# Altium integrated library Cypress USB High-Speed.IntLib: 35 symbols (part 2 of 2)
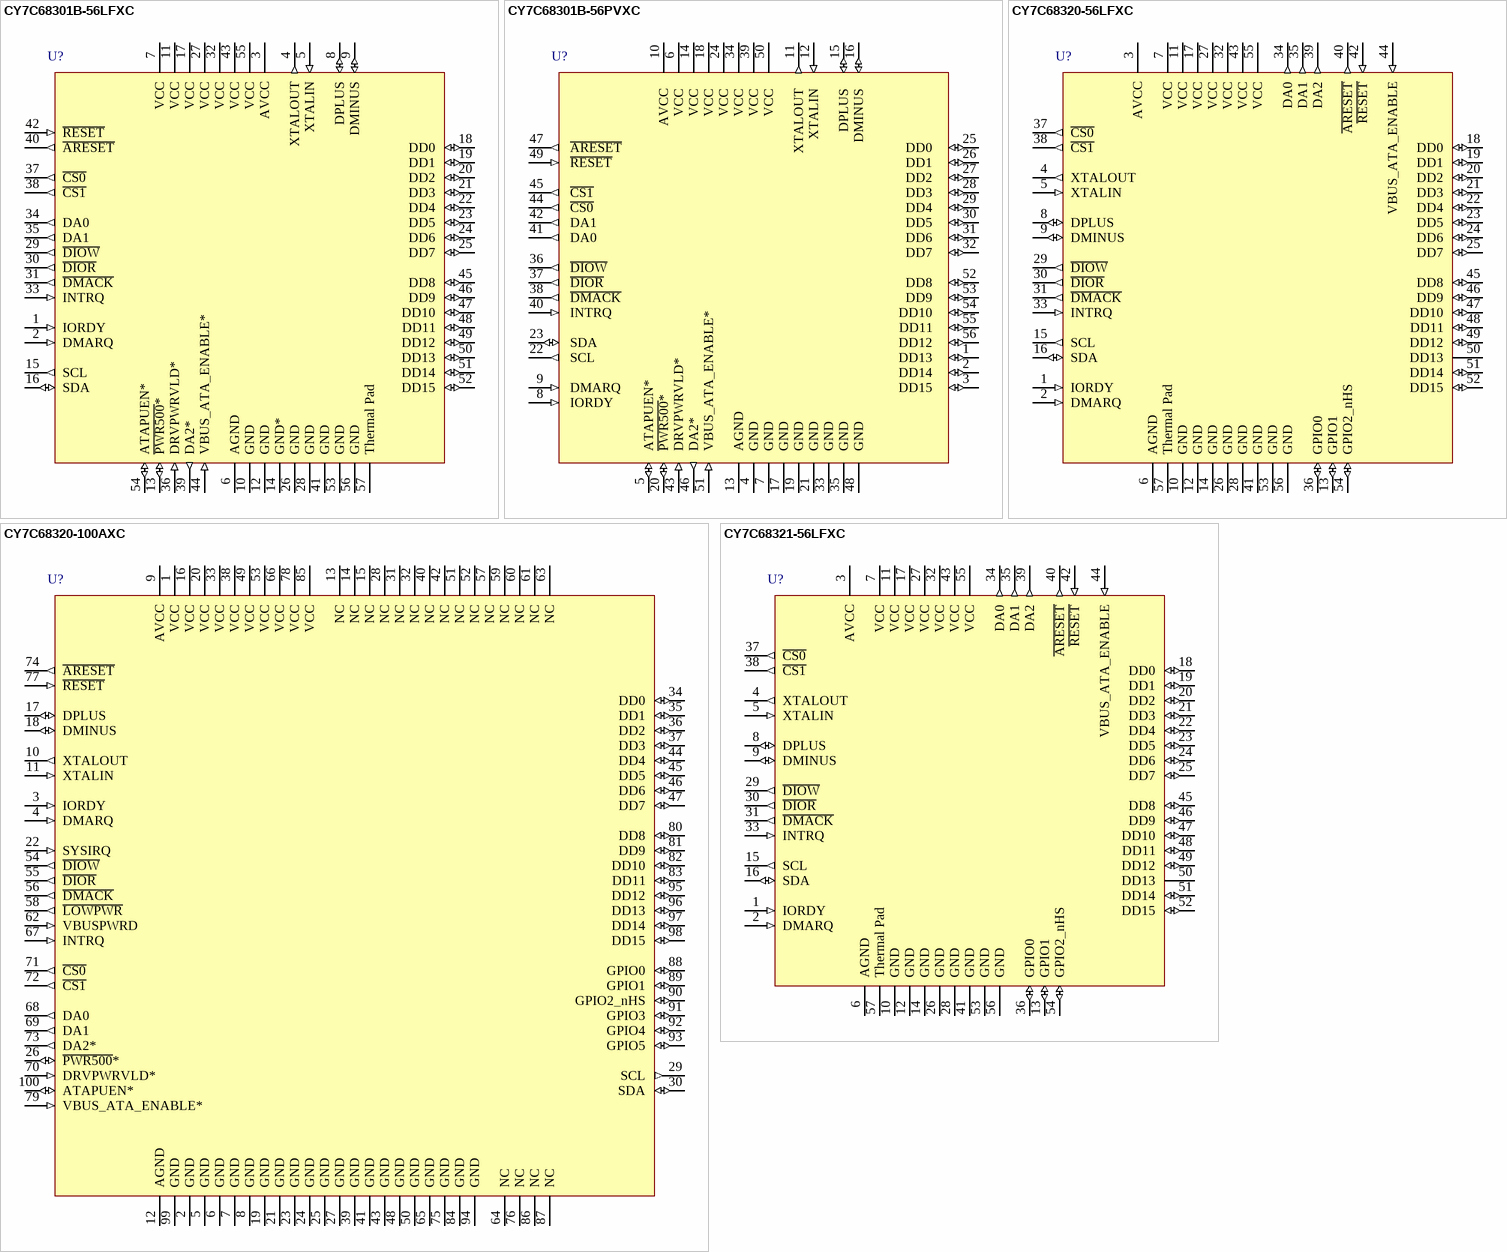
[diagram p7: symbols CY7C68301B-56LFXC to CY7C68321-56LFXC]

## CY7C68301B-56LFXC
designator U?
EZ-USB AT2LP USB2.0 to ATA/ATAPI Bridge for Battery Powered Designs, 56-Pin QFN, Pb-Free; Note: Pin names with Asterisk denote Pin Functionality during CY7C68300A Compatibility mode
footprint LF56A_N (QFN, 56-Leads, Body 8x8mm, Pitch 0.5mm, IPC Medium Density)
footprint LF56A_L (QFN, 56-Leads, Body 8x8mm, Pitch 0.5mm, IPC High Density)
footprint LF56A_M (QFN, 56-Leads, Body 8x8mm, Pitch 0.5mm, IPC Low Density)
pins: 1 IORDY (in), 2 DMARQ (in), 3 AVCC (power), 4 XTALOUT (out), 5 XTALIN (in), 6 AGND (power), 7 VCC (power), 8 DPLUS (io), 9 DMINUS (io), 10 GND (power), 11 VCC (power), 12 GND (power), 13 ~{PWR500}* (io) "(PU 10K)", 14 GND* (power) "(RESERVED)", 15 SCL (out), 16 SDA (io), 17 VCC (power), 18 DD0 (io), 19 DD1 (io), 20 DD2 (io), 21 DD3 (io), 22 DD4 (io), 23 DD5 (io), 24 DD6 (io), 25 DD7 (io), 26 GND (power), 27 VCC (power), 28 GND (power), 29 ~{DIOW} (out), 30 ~{DIOR} (out), 31 ~{DMACK} (out), 32 VCC (power), 33 INTRQ (in), 34 DA0 (out), 35 DA1 (out), 36 DRVPWRVLD* (in) "(DA2)", 37 ~{CS0} (out), 38 ~{CS1} (out), 39 DA2* (out) "(VBUS_PWR_VALID)", 40 ~{ARESET} (out), 41 GND (power), 42 ~{RESET} (in), 43 VCC (power), 44 VBUS_ATA_ENABLE* (in) "(ATA_EN)", 45 DD8 (io), 46 DD9 (io), 47 DD10 (io), 48 DD11 (io), 49 DD12 (io), 50 DD13 (io), 51 DD14 (io), 52 DD15 (io), 53 GND (power), 54 ATAPUEN* (io) "(NC)", 55 VCC (power), 56 GND (power), 57 Thermal Pad (power)

## CY7C68301B-56PVXC
designator U?
EZ-USB AT2LP USB2.0 to ATA/ATAPI Bridge for Battery Powered Designs, 56-Pin SSOP, Pb-Free; Note: Pin names with Asterisk denote Pin Functionality during CY7C68300A Compatibility mode
footprint O56 (SSOP; 56 Leads; Body Width 7.5 mm; Pitch 0.635 mm)
pins: 1  DD13   (io), 2  DD14   (io), 3  DD15   (io), 4  GND   (power), 5  ATAPUEN* (io) "(NC)", 6  VCC   (power), 7  GND   (power), 8  IORDY   (in), 9  DMARQ   (in), 10  AVCC   (power), 11  XTALOUT   (out), 12  XTALIN   (in), 13  AGND   (power), 14  VCC   (power), 15  DPLUS   (io), 16  DMINUS   (io), 17  GND   (power), 18  VCC   (power), 19  GND   (power), 20  ~{PWR500}* (io) "(PU 10K)", 21  GND (power) "(RESERVED)", 22  SCL   (out), 23  SDA   (io), 24  VCC   (power), 25  DD0   (io), 26  DD1   (io), 27  DD2   (io), 28  DD3   (io), 29  DD4   (io), 30  DD5   (io), 31  DD6   (io), 32  DD7   (io), 33  GND   (power), 34  VCC   (power), 35  GND   (power), 36  ~{DIOW} (out), 37  ~{DIOR} (out), 38  ~{DMACK} (out), 39  VCC   (power), 40  INTRQ   (in), 41  DA0   (out), 42  DA1   (out), 43  DRVPWRVLD* (in) "(DA2)", 44  ~{CS0} (out), 45  ~{CS1} (out), 46  DA2* (out) "(VBUS_PWR_VALID)", 47  ~{ARESET} (out), 48  GND   (power), 49  ~{RESET}   (in), 50  VCC   (power), 51  VBUS_ATA_ENABLE* (in) "(ATA_EN)", 52  DD8   (io), 53  DD9   (io), 54  DD10   (io), 55  DD11   (io), 56  DD12   (io)

## CY7C68320-56LFXC
designator U?
EZ-USB AT2LP USB2.0 to ATA/ATAPI Bridge for Self/ Bus Powered Designs, 56-Pin QFN, Pb-Free
footprint LF56A_N (QFN, 56-Leads, Body 8x8mm, Pitch 0.5mm, IPC Medium Density)
footprint LF56A_L (QFN, 56-Leads, Body 8x8mm, Pitch 0.5mm, IPC High Density)
footprint LF56A_M (QFN, 56-Leads, Body 8x8mm, Pitch 0.5mm, IPC Low Density)
pins: 1 IORDY (in), 2 DMARQ (in), 3 AVCC (power), 4 XTALOUT (out), 5 XTALIN (in), 6 AGND (power), 7 VCC (power), 8 DPLUS (io), 9 DMINUS (io), 10 GND (power), 11 VCC (power), 12 GND (power), 13 GPIO1 (io), 14 GND (power), 15 SCL (out), 16 SDA (io), 17 VCC (power), 18 DD0 (io), 19 DD1 (io), 20 DD2 (io), 21 DD3 (io), 22 DD4 (io), 23 DD5 (io), 24 DD6 (io), 25 DD7 (io), 26 GND (power), 27 VCC (power), 28 GND (power), 29 ~{DIOW} (out), 30 ~{DIOR} (out), 31 ~{DMACK} (out), 32 VCC (power), 33 INTRQ (in), 34 DA0 (out), 35 DA1 (out), 36 GPIO0 (io), 37 ~{CS0} (out), 38 ~{CS1} (out), 39 DA2 (out), 40 ~{ARESET} (out), 41 GND (power), 42 ~{RESET} (in), 43 VCC (power), 44 VBUS_ATA_ENABLE (in), 45 DD8 (io), 46 DD9 (io), 47 DD10 (io), 48 DD11 (io), 49 DD12 (io), 50 DD13 (power), 51 DD14 (io), 52 DD15 (io), 53 GND (power), 54 GPIO2_nHS (io), 55 VCC (power), 56 GND (power), 57 Thermal Pad (power)

## CY7C68320-100AXC
designator U?
EZ-USB AT2LP USB2.0 to ATA/ATAPI Bridge for Self/ Bus Powered Designs, 100-Pin TQFP, Pb-Free
footprint A101_N (Thin QFP, 100-Leads, Body 20x14mm, Pitch 0.65mm, IPC Medium Density)
footprint A101_L (Thin QFP, 100-Leads, Body 20x14mm, Pitch 0.65mm, IPC High Density)
footprint A101_M (Thin QFP, 100-Leads, Body 20x14mm, Pitch 0.65mm, IPC Low Density)
pins: 1 VCC (power), 2 GND (power), 3 IORDY (in), 4 DMARQ (in), 5 GND (power), 6 GND (power), 7 GND (power), 8 GND (power), 9 AVCC (power), 10 XTALOUT (out), 11 XTALIN (in), 12 AGND (power), 13 NC, 14 NC, 15 NC, 16 VCC (power), 17 DPLUS (io), 18 DMINUS (io), 19 GND (power), 20 VCC (power), 21 GND (power), 22 SYSIRQ (in), 23 GND (power), 24 GND (power), 25 GND (power), 26 ~{PWR500}* (io) "(PU10K)", 27 GND (power) "(RESERVED)", 28 NC, 29 SCL (out), 30 SDA (io), 31 NC, 32 NC, 33 VCC (power), 34 DD0 (io), 35 DD1 (io), 36 DD2 (io), 37 DD3 (io), 38 VCC (power), 39 GND (power), 40 NC, 41 GND (power), 42 NC, 43 GND (power), 44 DD4 (io), 45 DD5 (io), 46 DD6 (io), 47 DD7 (io), 48 GND (power), 49 VCC (power), 50 GND (power), 51 NC, 52 NC, 53 VCC (power), 54 ~{DIOW} (out), 55 ~{DIOR} (out), 56 ~{DMACK} (out), 57 NC, 58 ~{LOWPWR} (out), 59 NC, 60 NC, 61 NC, 62 VBUSPWRD (in), 63 NC, 64 NC, 65 GND (power), 66 VCC (power), 67 INTRQ (in), 68 DA0 (out), 69 DA1 (out), 70 DRVPWRVLD* (in) "(DA2)", 71 ~{CS0} (out), 72 ~{CS1} (out), 73 DA2* (out) "(VBUS_PWR_VALID)", 74 ~{ARESET} (out), 75 GND (power), 76 NC, 77 ~{RESET} (in), 78 VCC (power), 79 VBUS_ATA_ENABLE* (in) "(ATA_EN)", 80 DD8 (io), 81 DD9 (io), 82 DD10 (io), 83 DD11 (io), 84 GND (power), 85 VCC (power), 86 NC, 87 NC, 88 GPIO0 (io), 89 GPIO1 (io), 90 GPIO2_nHS (io), 91 GPIO3 (io), 92 GPIO4 (io), 93 GPIO5 (io), 94 GND (power), 95 DD12 (io), 96 DD13 (io), 97 DD14 (io), 98 DD15 (io), 99 GND (power), 100 ATAPUEN* (io) "(NC)"

## CY7C68321-56LFXC
designator U?
EZ-USB AT2LP USB2.0 to ATA/ATAPI Bridge for Battery Powered Designs, 56-Pin QFN, Pb-Free
footprint LF56A_N (QFN, 56-Leads, Body 8x8mm, Pitch 0.5mm, IPC Medium Density)
footprint LF56A_L (QFN, 56-Leads, Body 8x8mm, Pitch 0.5mm, IPC High Density)
footprint LF56A_M (QFN, 56-Leads, Body 8x8mm, Pitch 0.5mm, IPC Low Density)
pins: 1 IORDY (in), 2 DMARQ (in), 3 AVCC (power), 4 XTALOUT (out), 5 XTALIN (in), 6 AGND (power), 7 VCC (power), 8 DPLUS (io), 9 DMINUS (io), 10 GND (power), 11 VCC (power), 12 GND (power), 13 GPIO1 (io), 14 GND (power), 15 SCL (out), 16 SDA (io), 17 VCC (power), 18 DD0 (io), 19 DD1 (io), 20 DD2 (io), 21 DD3 (io), 22 DD4 (io), 23 DD5 (io), 24 DD6 (io), 25 DD7 (io), 26 GND (power), 27 VCC (power), 28 GND (power), 29 ~{DIOW} (out), 30 ~{DIOR} (out), 31 ~{DMACK} (out), 32 VCC (power), 33 INTRQ (in), 34 DA0 (out), 35 DA1 (out), 36 GPIO0 (io), 37 ~{CS0} (out), 38 ~{CS1} (out), 39 DA2 (out), 40 ~{ARESET} (out), 41 GND (power), 42 ~{RESET} (in), 43 VCC (power), 44 VBUS_ATA_ENABLE (in), 45 DD8 (io), 46 DD9 (io), 47 DD10 (io), 48 DD11 (io), 49 DD12 (io), 50 DD13 (power), 51 DD14 (io), 52 DD15 (io), 53 GND (power), 54 GPIO2_nHS (io), 55 VCC (power), 56 GND (power), 57 Thermal Pad (power)

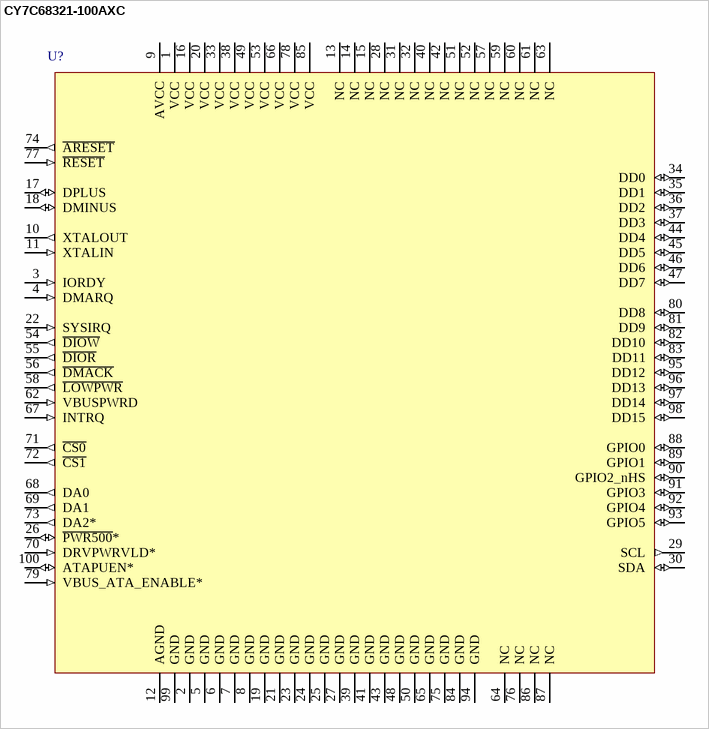
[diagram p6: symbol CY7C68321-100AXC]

## CY7C68321-100AXC
designator U?
EZ-USB AT2LP USB2.0 to ATA/ATAPI Bridge for Battery Powered Designs, 100-Pin TQFP, Pb-Free
footprint A101_N (Thin QFP, 100-Leads, Body 20x14mm, Pitch 0.65mm, IPC Medium Density)
footprint A101_L (Thin QFP, 100-Leads, Body 20x14mm, Pitch 0.65mm, IPC High Density)
footprint A101_M (Thin QFP, 100-Leads, Body 20x14mm, Pitch 0.65mm, IPC Low Density)
pins: 1 VCC (power), 2 GND (power), 3 IORDY (in), 4 DMARQ (in), 5 GND (power), 6 GND (power), 7 GND (power), 8 GND (power), 9 AVCC (power), 10 XTALOUT (out), 11 XTALIN (in), 12 AGND (power), 13 NC, 14 NC, 15 NC, 16 VCC (power), 17 DPLUS (io), 18 DMINUS (io), 19 GND (power), 20 VCC (power), 21 GND (power), 22 SYSIRQ (in), 23 GND (power), 24 GND (power), 25 GND (power), 26 ~{PWR500}* (io) "(PU10K)", 27 GND (power) "(RESERVED)", 28 NC, 29 SCL (out), 30 SDA (io), 31 NC, 32 NC, 33 VCC (power), 34 DD0 (io), 35 DD1 (io), 36 DD2 (io), 37 DD3 (io), 38 VCC (power), 39 GND (power), 40 NC, 41 GND (power), 42 NC, 43 GND (power), 44 DD4 (io), 45 DD5 (io), 46 DD6 (io), 47 DD7 (io), 48 GND (power), 49 VCC (power), 50 GND (power), 51 NC, 52 NC, 53 VCC (power), 54 ~{DIOW} (out), 55 ~{DIOR} (out), 56 ~{DMACK} (out), 57 NC, 58 ~{LOWPWR} (out), 59 NC, 60 NC, 61 NC, 62 VBUSPWRD (in), 63 NC, 64 NC, 65 GND (power), 66 VCC (power), 67 INTRQ (in), 68 DA0 (out), 69 DA1 (out), 70 DRVPWRVLD* (in) "(DA2)", 71 ~{CS0} (out), 72 ~{CS1} (out), 73 DA2* (out) "(VBUS_PWR_VALID)", 74 ~{ARESET} (out), 75 GND (power), 76 NC, 77 ~{RESET} (in), 78 VCC (power), 79 VBUS_ATA_ENABLE* (in) "(ATA_EN)", 80 DD8 (io), 81 DD9 (io), 82 DD10 (io), 83 DD11 (io), 84 GND (power), 85 VCC (power), 86 NC, 87 NC, 88 GPIO0 (io), 89 GPIO1 (io), 90 GPIO2_nHS (io), 91 GPIO3 (io), 92 GPIO4 (io), 93 GPIO5 (io), 94 GND (power), 95 DD12 (io), 96 DD13 (io), 97 DD14 (io), 98 DD15 (io), 99 GND (power), 100 ATAPUEN* (io) "(NC)"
